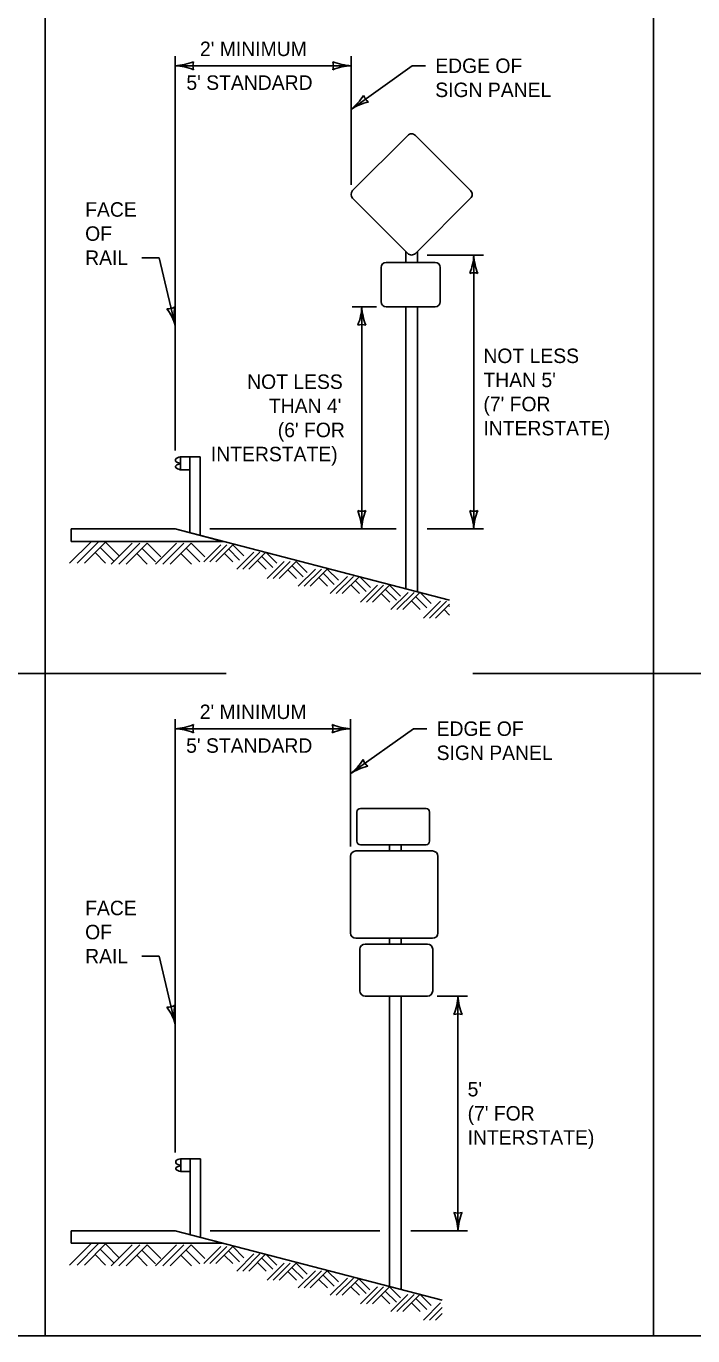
# Model space of a CAD drawing. Extents: x 49991.4 to 50021, y 49987.6 to 50011.4.
# Drawn here: x 50003.15 to 50005.92, y 49987.8 to 49993.23 of the extents above; entities that cross this region are included whole.
import ezdxf

# ---------------------------------------------------------------- set-up
doc = ezdxf.new("R2010")
doc.units = 0
for name, color, linetype in [('Level 1', 7, 'Continuous'), ('Level 2', 7, 'Continuous'), ('Level 3', 7, 'Continuous')]:
    doc.layers.add(name, color=color, linetype=linetype)

msp = doc.modelspace()

# ---------------------------------------------------------------- linework, layer by layer
at = {"layer": 'Level 1'}
for p, q in [((50004.5041, 49992.5484), (50004.7327, 49992.7772)), ((50004.7645, 49992.7772), (50004.9934, 49992.5484)), ((50004.7327, 49992.2877), (50004.5041, 49992.5166)), ((50004.9934, 49992.5166), (50004.7645, 49992.2877)), ((50004.7243, 49992.2506), (50004.7243, 49992.2961)), ((50004.7729, 49992.2506), (50004.7729, 49992.2961)), ((50004.622, 49992.0878), (50004.622, 49992.2291)), ((50004.6435, 49992.2506), (50004.8461, 49992.2506)), ((50004.8676, 49992.2291), (50004.8676, 49992.0878)), ((50004.8461, 49992.0663), (50004.6435, 49992.0663)), ((50004.7243, 49990.8966), (50004.7243, 49992.0663)), ((50004.7729, 49990.884), (50004.7729, 49992.0663)), ((50003.8289, 49991.4443), (50003.7883, 49991.4443)), ((50003.7883, 49991.391), (50003.8289, 49991.391)), ((50003.7901, 49991.4443), (50003.7901, 49991.391)), ((50003.8289, 49991.129), (50003.8289, 49991.4443)), ((50003.8718, 49991.4443), (50003.8289, 49991.4443)), ((50003.8718, 49991.1182), (50003.8718, 49991.4443)), ((50003.768, 49991.1452), (50003.336, 49991.1452)), ((50003.336, 49991.1452), (50003.336, 49991.0935)), ((50003.768, 49991.1452), (50003.336, 49991.1452)), ((50003.336, 49991.1452), (50003.336, 49991.0935)), ((50003.7682, 49991.1452), (50004.9063, 49990.8493)), ((50003.9668, 49991.0936), (50003.7682, 49991.1452)), ((50003.3298, 49991.0029), (50003.4171, 49991.0903)), ((50003.336, 49991.0935), (50003.9668, 49991.0935)), ((50003.336, 49991.0935), (50003.9668, 49991.0935)), ((50003.3605, 49991.0029), (50003.4478, 49991.0903)), ((50003.3909, 49991.0029), (50003.4782, 49991.0903)), ((50003.4568, 49991.0687), (50003.5135, 49991.012)), ((50003.4782, 49991.0903), (50003.5351, 49991.0335)), ((50003.5026, 49990.9993), (50003.5899, 49991.0866)), ((50003.5333, 49990.9993), (50003.6206, 49991.0866)), ((50003.5637, 49990.9993), (50003.6511, 49991.0866)), ((50003.6511, 49991.0866), (50003.7079, 49991.0299)), ((50003.6861, 49990.9993), (50003.7734, 49991.0866)), ((50003.7168, 49990.9993), (50003.8041, 49991.0866)), ((50003.7472, 49990.9993), (50003.8346, 49991.0866)), ((50003.8346, 49991.0866), (50003.8914, 49991.0299)), ((50003.8863, 49991.0088), (50003.9571, 49991.0795)), ((50003.9112, 49991.0088), (50003.9819, 49991.0795)), ((50003.9358, 49991.0088), (50004.0065, 49991.0795)), ((50003.9665, 49991.0935), (50003.9665, 49991.0935)), ((50003.9668, 49991.0935), (50003.9668, 49991.0936)), ((50004.0065, 49991.0795), (50004.0526, 49991.0335)), ((50003.4351, 49991.047), (50003.4792, 49991.0029)), ((50003.6079, 49991.0433), (50003.652, 49990.9993)), ((50003.6295, 49991.065), (50003.6862, 49991.0084)), ((50003.7914, 49991.0433), (50003.8355, 49990.9993)), ((50003.813, 49991.065), (50003.8697, 49991.0084)), ((50003.9716, 49991.0445), (50004.0075, 49991.0088)), ((50003.9891, 49991.0621), (50004.0352, 49991.0162)), ((50004.0238, 49990.9781), (50004.0945, 49991.0488)), ((50004.0486, 49990.9781), (50004.1193, 49991.0488)), ((50004.0732, 49990.9781), (50004.143, 49991.0477)), ((50004.109, 49991.0137), (50004.1449, 49990.9781)), ((50004.1266, 49991.0314), (50004.1726, 49990.9855)), ((50004.1459, 49991.047), (50004.19, 49991.0028)), ((50004.1495, 49990.9398), (50004.2202, 49991.0105)), ((50004.1744, 49990.9398), (50004.2451, 49991.0105)), ((50004.199, 49990.9398), (50004.2697, 49991.0105)), ((50004.2348, 49990.9755), (50004.2706, 49990.9398)), ((50004.2524, 49990.9931), (50004.2983, 49990.9472)), ((50004.2697, 49991.0105), (50004.3158, 49990.9645)), ((50004.2786, 49990.908), (50004.3493, 49990.9788)), ((50004.3036, 49990.908), (50004.3743, 49990.9788)), ((50004.3282, 49990.908), (50004.3989, 49990.9788)), ((50004.3814, 49990.9613), (50004.4274, 49990.9154)), ((50004.3989, 49990.9788), (50004.445, 49990.9327)), ((50004.3639, 49990.9436), (50004.3997, 49990.908)), ((50004.4114, 49990.8775), (50004.4821, 49990.9482)), ((50004.4362, 49990.8775), (50004.5071, 49990.9482)), ((50004.461, 49990.8775), (50004.5305, 49990.947)), ((50004.4967, 49990.9132), (50004.5324, 49990.8775)), ((50004.5142, 49990.9308), (50004.5602, 49990.8851)), ((50004.5338, 49990.9462), (50004.5778, 49990.9024)), ((50004.5369, 49990.8418), (50004.6076, 49990.9126)), ((50004.5619, 49990.8418), (50004.6326, 49990.9126)), ((50004.5864, 49990.8418), (50004.6571, 49990.9126)), ((50004.6571, 49990.9126), (50004.7033, 49990.8665)), ((50004.6222, 49990.8775), (50004.6579, 49990.8418)), ((50004.6396, 49990.8951), (50004.6857, 49990.8492)), ((50004.6631, 49990.8107), (50004.7339, 49990.8814)), ((50004.688, 49990.8107), (50004.7588, 49990.8814)), ((50004.7126, 49990.8107), (50004.7834, 49990.8813)), ((50004.766, 49990.864), (50004.812, 49990.8181)), ((50004.7837, 49990.8812), (50004.8295, 49990.8355)), ((50004.7485, 49990.8464), (50004.7842, 49990.8107)), ((50004.7985, 49990.7748), (50004.8692, 49990.8455)), ((50004.8235, 49990.7748), (50004.8942, 49990.8455)), ((50004.848, 49990.7748), (50004.9063, 49990.833)), ((50004.8839, 49990.8105), (50004.9063, 49990.7882)), ((50004.9013, 49990.8281), (50004.9063, 49990.8231)), ((50004.5364, 49989.9861), (50004.8085, 49989.9861)), ((50004.5214, 49989.8499), (50004.5214, 49989.9711)), ((50004.8235, 49989.9711), (50004.8235, 49989.8499)), ((50004.8085, 49989.8349), (50004.5364, 49989.8349)), ((50004.6569, 49989.8098), (50004.6569, 49989.8349)), ((50004.7055, 49989.8098), (50004.7055, 49989.8349)), ((50004.4955, 49989.4698), (50004.4955, 49989.7873)), ((50004.518, 49989.8098), (50004.8356, 49989.8098)), ((50004.8581, 49989.7873), (50004.8581, 49989.4698)), ((50004.8356, 49989.4473), (50004.518, 49989.4473)), ((50004.6569, 49989.4234), (50004.6569, 49989.4473)), ((50004.7055, 49989.4234), (50004.7055, 49989.4473)), ((50004.5342, 49989.229), (50004.5342, 49989.4019)), ((50004.5557, 49989.4234), (50004.8149, 49989.4234)), ((50004.8364, 49989.4019), (50004.8364, 49989.229)), ((50004.8149, 49989.2075), (50004.5557, 49989.2075)), ((50004.6569, 49988.0034), (50004.6569, 49989.2075)), ((50004.7056, 49987.9907), (50004.7056, 49989.2075)), ((50003.8302, 49988.5334), (50003.7896, 49988.5334)), ((50003.7914, 49988.5334), (50003.7914, 49988.4801)), ((50003.8302, 49988.2183), (50003.8302, 49988.5334)), ((50003.8731, 49988.5334), (50003.8302, 49988.5334)), ((50003.8731, 49988.2072), (50003.8731, 49988.5334)), ((50003.7896, 49988.4801), (50003.8302, 49988.4801)), ((50003.768, 49988.2345), (50003.336, 49988.2345)), ((50003.336, 49988.2345), (50003.336, 49988.1829)), ((50003.768, 49988.2345), (50003.336, 49988.2345)), ((50003.336, 49988.2345), (50003.336, 49988.1829)), ((50003.7682, 49988.2345), (50004.875, 49987.9467)), ((50003.9666, 49988.1829), (50003.7682, 49988.2345)), ((50003.3298, 49988.0923), (50003.4171, 49988.1796)), ((50003.336, 49988.1829), (50003.9667, 49988.1829)), ((50003.336, 49988.1829), (50003.9666, 49988.1829)), ((50003.3605, 49988.0923), (50003.4478, 49988.1796)), ((50003.3909, 49988.0923), (50003.4782, 49988.1796)), ((50003.435, 49988.1363), (50003.4792, 49988.0923)), ((50003.4568, 49988.158), (50003.5135, 49988.1014)), ((50003.4782, 49988.1796), (50003.5351, 49988.1228)), ((50003.5026, 49988.0886), (50003.5899, 49988.176)), ((50003.5333, 49988.0886), (50003.6206, 49988.176)), ((50003.5637, 49988.0886), (50003.651, 49988.176)), ((50003.6079, 49988.1327), (50003.652, 49988.0886)), ((50003.6295, 49988.1544), (50003.6862, 49988.0977)), ((50003.651, 49988.176), (50003.7079, 49988.1192)), ((50003.6861, 49988.0886), (50003.7734, 49988.176)), ((50003.7168, 49988.0886), (50003.8041, 49988.176)), ((50003.7472, 49988.0886), (50003.8345, 49988.176)), ((50003.7914, 49988.1327), (50003.8355, 49988.0886)), ((50003.813, 49988.1544), (50003.8697, 49988.0977)), ((50003.8345, 49988.176), (50003.8914, 49988.1192)), ((50003.8863, 49988.0981), (50003.957, 49988.1688)), ((50003.9112, 49988.0981), (50003.9819, 49988.1688)), ((50003.9358, 49988.0981), (50004.0065, 49988.1688)), ((50003.9665, 49988.1829), (50003.9665, 49988.1829)), ((50003.9716, 49988.1339), (50004.0075, 49988.0981)), ((50003.9891, 49988.1515), (50004.0351, 49988.1055)), ((50004.0065, 49988.1688), (50004.0526, 49988.1228)), ((50004.0237, 49988.0674), (50004.0944, 49988.1381)), ((50004.0486, 49988.0674), (50004.1193, 49988.1381)), ((50004.0732, 49988.0674), (50004.143, 49988.1371)), ((50004.1458, 49988.1363), (50004.19, 49988.0922)), ((50004.109, 49988.1031), (50004.1449, 49988.0674)), ((50004.1266, 49988.1208), (50004.1725, 49988.0748)), ((50004.1495, 49988.0291), (50004.2202, 49988.0998)), ((50004.1744, 49988.0291), (50004.2451, 49988.0998)), ((50004.199, 49988.0291), (50004.2697, 49988.0998)), ((50004.2524, 49988.0825), (50004.2983, 49988.0365)), ((50004.2697, 49988.0998), (50004.3158, 49988.0538)), ((50004.2348, 49988.0649), (50004.2705, 49988.0291)), ((50004.2785, 49987.9973), (50004.3493, 49988.0681)), ((50004.3035, 49987.9973), (50004.3742, 49988.0681)), ((50004.3282, 49987.9973), (50004.3989, 49988.0681)), ((50004.3639, 49988.033), (50004.3997, 49987.9973)), ((50004.3814, 49988.0507), (50004.4274, 49988.0047)), ((50004.3989, 49988.0681), (50004.4449, 49988.0221)), ((50004.4113, 49987.9669), (50004.4821, 49988.0376)), ((50004.4362, 49987.9669), (50004.507, 49988.0376)), ((50004.461, 49987.9669), (50004.5298, 49988.0357)), ((50004.5298, 49988.0357), (50004.5757, 49987.9899)), ((50004.4967, 49988.0025), (50004.5324, 49987.9669)), ((50004.5142, 49988.0201), (50004.5602, 49987.9744)), ((50004.5369, 49987.9311), (50004.6076, 49988.0019)), ((50004.5619, 49987.9311), (50004.6326, 49988.0019)), ((50004.5864, 49987.9311), (50004.6571, 49988.0019)), ((50004.6396, 49987.9845), (50004.6857, 49987.9385)), ((50004.6571, 49988.0019), (50004.7033, 49987.9558)), ((50004.6631, 49987.9), (50004.7338, 49987.9708)), ((50004.688, 49987.9), (50004.7588, 49987.9708)), ((50004.7126, 49987.9), (50004.7832, 49987.9706)), ((50004.7838, 49987.9704), (50004.8295, 49987.9248)), ((50004.6221, 49987.9669), (50004.6579, 49987.9311)), ((50004.7485, 49987.9357), (50004.7842, 49987.9)), ((50004.766, 49987.9533), (50004.8119, 49987.9074)), ((50004.7985, 49987.8641), (50004.8692, 49987.9349)), ((50004.8235, 49987.8641), (50004.875, 49987.9157)), ((50004.848, 49987.8641), (50004.875, 49987.8911))]:
    msp.add_line(p, q, dxfattribs=at)
msp.add_lwpolyline([(49999.3835, 49998.9992), (50016.7501, 49998.9992), (50016.7501, 49987.7988), (49999.3835, 49987.7988)], close=True, dxfattribs=at)
for centre, radius, start, end in [((50004.7486, 49992.7613), 0.0225, 45.011, 135.022), ((50004.52, 49992.5325), 0.0225, 135.022, 224.967), ((50004.9774, 49992.5325), 0.0225, 315, 45.011), ((50004.7486, 49992.3036), 0.0225, 224.967, 315), ((50004.6435, 49992.2291), 0.0215, 90, 180), ((50004.8461, 49992.2291), 0.0215, 0, 90), ((50004.6435, 49992.0878), 0.0215, 180, 270), ((50004.8461, 49992.0878), 0.0215, 270, 0), ((50004.5364, 49989.9711), 0.015, 90, 180), ((50004.8085, 49989.9711), 0.015, 0, 90), ((50004.5364, 49989.8499), 0.015, 180, 270), ((50004.8085, 49989.8499), 0.015, 270, 0), ((50004.518, 49989.7873), 0.0225, 90, 180), ((50004.8356, 49989.7873), 0.0225, 0, 90), ((50004.518, 49989.4698), 0.0225, 180, 270), ((50004.8356, 49989.4698), 0.0225, 270, 0), ((50004.5557, 49989.4019), 0.0215, 90, 180), ((50004.8149, 49989.4019), 0.0215, 0, 90), ((50004.5557, 49989.229), 0.0215, 180, 270), ((50004.8149, 49989.229), 0.0215, 270, 0)]:
    msp.add_arc(centre, radius, start, end, dxfattribs=at)
for points in [[(50003.7883, 49991.4443), (50003.7696, 49991.4337), (50003.7692, 49991.4267), (50003.7883, 49991.4176), (50003.789, 49991.4174), (50003.7692, 49991.4062), (50003.7696, 49991.4025), (50003.7883, 49991.391)], [(50003.7896, 49988.5334), (50003.7709, 49988.5228), (50003.7705, 49988.5158), (50003.7896, 49988.5067), (50003.7903, 49988.5065), (50003.7705, 49988.4953), (50003.7709, 49988.4916), (50003.7896, 49988.4801)]]:
    msp.add_spline(points, degree=3, dxfattribs=at)
at = {"layer": 'Level 3'}
for p, q in [((50003.2287, 49987.7988), (50003.2287, 49998.9992)), ((50005.7525, 49987.7988), (50005.7525, 49998.9992)), ((50003.768, 49991.471), (50003.768, 49993.1063)), ((50004.4975, 49992.5725), (50004.4975, 49993.1063)), ((50004.4975, 49993.0663), (50003.768, 49993.0663)), ((50004.4975, 49992.8854), (50004.7515, 49993.0663)), ((50004.7515, 49993.0663), (50004.8069, 49993.0663)), ((50003.6292, 49992.2702), (50003.7012, 49992.2702)), ((50003.7012, 49992.2702), (50003.768, 49991.9887)), ((50004.8129, 49992.2811), (50005.0467, 49992.2811)), ((50005.0067, 49992.2811), (50005.0067, 49991.1452)), ((50004.502, 49992.0663), (50004.6035, 49992.0663)), ((50004.542, 49991.1452), (50004.542, 49992.0663)), ((50003.9118, 49991.1452), (50004.6843, 49991.1452)), ((50004.8129, 49991.1452), (50005.0467, 49991.1452)), ((50002.4787, 49990.5461), (50003.9787, 49990.5461)), ((50005.0025, 49990.5461), (50006.5025, 49990.5461)), ((50003.768, 49988.5593), (50003.768, 49990.3568)), ((50004.4955, 49990.3168), (50003.768, 49990.3168)), ((50004.4955, 49989.8286), (50004.4955, 49990.3568)), ((50004.4955, 49990.1305), (50004.7572, 49990.3168)), ((50004.7572, 49990.3168), (50004.8126, 49990.3168)), ((50003.6292, 49989.3733), (50003.7012, 49989.3733)), ((50003.7012, 49989.3733), (50003.768, 49989.0918)), ((50004.8549, 49989.2075), (50004.9812, 49989.2075)), ((50004.9412, 49988.2345), (50004.9412, 49989.2075)), ((50003.9131, 49988.2345), (50004.6169, 49988.2345)), ((50004.7456, 49988.2345), (50004.9812, 49988.2345))]:
    msp.add_line(p, q, dxfattribs=at)
for centre, radius, start, end in [((50003.7565, 49993.299), 0.233, 272.8273, 292.0772), ((50003.8962, 49993.0663), 0.0548, 162.1388, 197.8612), ((50004.5067, 49993.2884), 0.2223, 247.456, 267.6395), ((50004.3693, 49993.0663), 0.0548, 342.1388, 17.8612), ((50003.7588, 49992.8442), 0.2223, 67.456, 87.6395), ((50004.509, 49992.8336), 0.233, 92.8273, 112.0772), ((50004.3531, 49993.0683), 0.233, 308.286, 327.5358), ((50004.6189, 49992.6992), 0.2223, 102.9147, 123.0982), ((50004.6019, 49992.9598), 0.0548, 197.5975, 233.3198), ((50004.7846, 49992.2903), 0.2223, 337.456, 357.6395), ((50005.2394, 49992.2926), 0.233, 182.8273, 202.0772), ((50005.0067, 49992.1529), 0.0548, 72.1388, 107.8612), ((50003.7376, 49992.1133), 0.0548, 265.8498, 301.5721), ((50003.5446, 49991.9224), 0.233, 16.5382, 35.7881), ((50003.986, 49992.0325), 0.2223, 171.1669, 191.3505), ((50004.3199, 49992.0755), 0.2223, 337.456, 357.6395), ((50004.7747, 49992.0778), 0.233, 182.8273, 202.0772), ((50004.542, 49991.9381), 0.0548, 72.1388, 107.8612), ((50004.542, 49991.2734), 0.0548, 252.1388, 287.8612), ((50004.3093, 49991.1337), 0.233, 2.8273, 22.0772), ((50004.7641, 49991.136), 0.2223, 157.456, 177.6395), ((50005.0067, 49991.2734), 0.0548, 252.1388, 287.8612), ((50004.774, 49991.1337), 0.233, 2.8273, 22.0772), ((50005.2288, 49991.136), 0.2223, 157.456, 177.6395), ((50003.7565, 49990.5495), 0.233, 272.8273, 292.0772), ((50003.7588, 49990.0947), 0.2223, 67.456, 87.6395), ((50003.8962, 49990.3168), 0.0548, 162.1388, 197.8612), ((50004.5047, 49990.5389), 0.2223, 247.456, 267.6395), ((50004.3673, 49990.3168), 0.0548, 342.1388, 17.8612), ((50004.507, 49990.0841), 0.233, 92.8273, 112.0772), ((50004.3512, 49990.3134), 0.233, 308.2738, 327.5236), ((50004.6169, 49989.9442), 0.2223, 102.9025, 123.086), ((50004.6, 49990.2049), 0.0548, 197.5853, 233.3076), ((50003.7376, 49989.2164), 0.0548, 265.8498, 301.5721), ((50003.986, 49989.1356), 0.2223, 171.1669, 191.3505), ((50004.7191, 49989.2167), 0.2223, 337.456, 357.6395), ((50005.1739, 49989.219), 0.233, 182.8273, 202.0772), ((50003.5446, 49989.0255), 0.233, 16.5382, 35.7881), ((50004.9412, 49989.0793), 0.0548, 72.1388, 107.8612), ((50004.9412, 49988.3627), 0.0548, 252.1388, 287.8612), ((50004.7085, 49988.223), 0.233, 2.8273, 22.0772), ((50005.1633, 49988.2253), 0.2223, 157.456, 177.6395)]:
    msp.add_arc(centre, radius, start, end, dxfattribs=at)

# ---------------------------------------------------------------- texts
at = {"layer": 'Level 2'}
for s, p in [("2' MINIMUM", (50003.8706, 49993.1063)), ('EDGE OF', (50004.8469, 49993.0363)), ("5' STANDARD", (50003.8142, 49992.9663)), ('SIGN PANEL', (50004.8469, 49992.9363)), ('FACE', (50003.3941, 49992.4402)), ('OF', (50003.3941, 49992.3402)), ('RAIL', (50003.3941, 49992.2402)), ('NOT LESS', (50005.0467, 49991.8332)), ('NOT LESS', (50004.0663, 49991.7258)), ("THAN 5'", (50005.0467, 49991.7332)), ("THAN 4'", (50004.1567, 49991.6258)), ("(7' FOR", (50005.0467, 49991.6332)), ("(6' FOR", (50004.1933, 49991.5258)), ('INTERSTATE)', (50005.0467, 49991.5332)), ('INTERSTATE)', (50003.9159, 49991.4258)), ("2' MINIMUM", (50003.8696, 49990.3568)), ('EDGE OF', (50004.8526, 49990.2868)), ("5' STANDARD", (50003.8132, 49990.2168)), ('SIGN PANEL', (50004.8526, 49990.1868)), ('FACE', (50003.3941, 49989.5433)), ('OF', (50003.3941, 49989.4433)), ('RAIL', (50003.3941, 49989.3433)), ("5'", (50004.9812, 49988.7916)), ("(7' FOR", (50004.9812, 49988.6916)), ('INTERSTATE)', (50004.9812, 49988.5916))]:
    msp.add_text(s, height=0.06, dxfattribs=at).set_placement(p)

doc.saveas('drawing.dxf')
